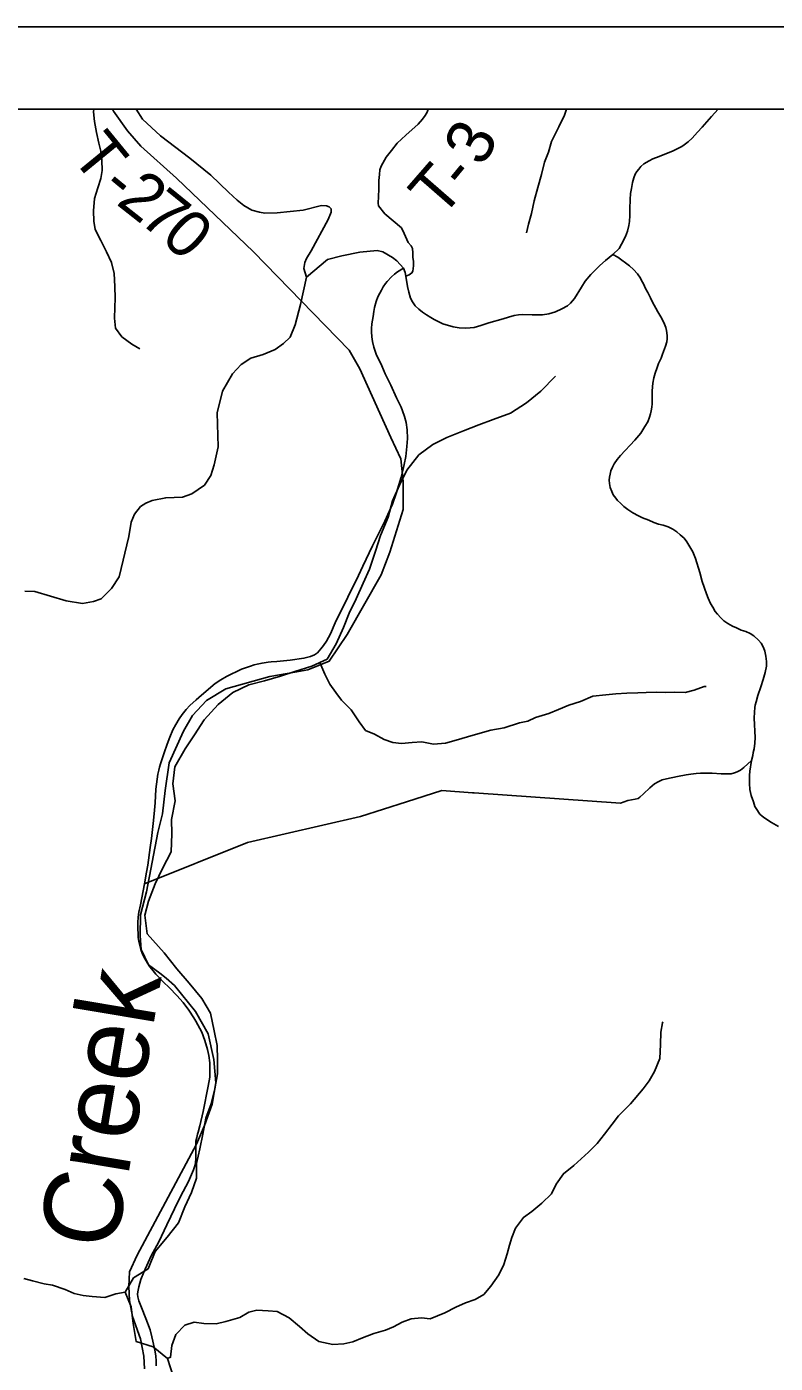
# Model space of a CAD drawing. Extents: x 0 to 34, y 0 to 22.
# Drawn here: x 2.84 to 3.746, y 19.381 to 21 of the extents above; entities that cross this region are included whole.
import ezdxf

# ---------------------------------------------------------------- set-up
doc = ezdxf.new("R2010")
doc.units = 0
for name, color, linetype in [('GM_X_County_Road', 7, 'Continuous'), ('GM_X_Minor_River', 7, 'Continuous'), ('GM_X_Minor_River_Text', 7, 'Continuous'), ('GM_X_Rail_Line', 7, 'Continuous'), ('GM_X_Township_Road', 7, 'Continuous'), ('GM_X_Township_Road_Text', 7, 'Continuous'), ('SH_Data', 7, 'Continuous')]:
    doc.layers.add(name, color=color, linetype=linetype)

msp = doc.modelspace()

# ---------------------------------------------------------------- linework, layer by layer
at = {"layer": 'GM_X_County_Road'}
msp.add_lwpolyline([(3.7501, 20.0312), (3.7416, 20.0362), (3.7334, 20.0413), (3.7303, 20.0439), (3.7276, 20.0464), (3.7258, 20.0486), (3.7245, 20.0509), (3.7216, 20.0556), (3.7197, 20.0611), (3.7172, 20.0689), (3.7156, 20.0762), (3.7149, 20.0833), (3.7151, 20.0889), (3.7151, 20.0931), (3.7155, 20.0985), (3.7174, 20.1112), (3.7189, 20.1175), (3.7196, 20.121), (3.7205, 20.1253), (3.7213, 20.1325), (3.7217, 20.1391), (3.7214, 20.1468), (3.7211, 20.155), (3.7208, 20.1624), (3.7211, 20.1698), (3.7216, 20.1757), (3.722, 20.1783), (3.7229, 20.1824), (3.7252, 20.1901), (3.7287, 20.2006), (3.7317, 20.2094), (3.7339, 20.2177), (3.7355, 20.2257), (3.7354, 20.2312), (3.7348, 20.2375), (3.7336, 20.2438), (3.7319, 20.2483), (3.729, 20.2536), (3.7261, 20.2572), (3.7201, 20.2624), (3.7158, 20.265), (3.7107, 20.2674), (3.7051, 20.2693), (3.6992, 20.272), (3.6943, 20.2742), (3.6887, 20.2772), (3.6841, 20.2804), (3.6803, 20.2839), (3.6763, 20.2884), (3.6735, 20.2919), (3.6705, 20.2969), (3.6677, 20.3016), (3.665, 20.3078), (3.6629, 20.3132), (3.6578, 20.3283), (3.6547, 20.339), (3.6495, 20.3559), (3.6462, 20.364), (3.6429, 20.3701), (3.6393, 20.376), (3.6358, 20.3804), (3.6312, 20.3848), (3.6271, 20.3882), (3.6223, 20.3914), (3.6167, 20.3942), (3.6106, 20.3963), (3.6049, 20.3977), (3.5993, 20.3995), (3.5931, 20.4022), (3.5855, 20.4052), (3.5807, 20.4075), (3.5736, 20.4112), (3.5675, 20.4153), (3.5627, 20.419), (3.5586, 20.4228), (3.5551, 20.4262), (3.5531, 20.429), (3.5501, 20.4331), (3.5482, 20.437), (3.5463, 20.4421), (3.5455, 20.4467), (3.5451, 20.4509), (3.5455, 20.4543), (3.5462, 20.458), (3.5472, 20.462), (3.5489, 20.4666), (3.5513, 20.4707), (3.5547, 20.4759), (3.5589, 20.4808), (3.5761, 20.4991), (3.5833, 20.5078), (3.5883, 20.5158), (3.5918, 20.5216), (3.594, 20.5273), (3.5953, 20.5313), (3.5961, 20.5348), (3.5966, 20.5391), (3.597, 20.5434), (3.5971, 20.5512), (3.597, 20.5554), (3.5972, 20.5588), (3.5975, 20.5638), (3.5979, 20.5685), (3.5993, 20.5746), (3.6006, 20.5804), (3.603, 20.5871), (3.605, 20.5922), (3.6079, 20.5987), (3.6098, 20.6034), (3.6122, 20.6097), (3.6133, 20.613), (3.6148, 20.6182), (3.6151, 20.6219), (3.6152, 20.6258), (3.615, 20.6291), (3.6145, 20.6321), (3.6137, 20.6357), (3.6119, 20.6398), (3.6088, 20.6466), (3.6041, 20.6547), (3.5973, 20.6674), (3.5951, 20.6715), (3.5918, 20.6783), (3.5891, 20.683), (3.5865, 20.6885), (3.5844, 20.6925), (3.5829, 20.6953), (3.5792, 20.7007), (3.5745, 20.7061), (3.5696, 20.7103), (3.5554, 20.721), (3.5493, 20.724)], dxfattribs=at)
at = {"layer": 'GM_X_Minor_River'}
for points in [[(2.9209, 20.9), (2.9206, 20.8969), (2.9217, 20.8852), (2.9244, 20.8719), (2.927, 20.859), (2.9293, 20.8492), (2.9308, 20.8382), (2.9312, 20.826), (2.9293, 20.8162), (2.9259, 20.8048), (2.9217, 20.7919), (2.9206, 20.7771), (2.9209, 20.7646), (2.9228, 20.7543), (2.9293, 20.7411), (2.9364, 20.7274), (2.9425, 20.7145), (2.9455, 20.7013), (2.9466, 20.6853), (2.947, 20.6713), (2.9466, 20.6599), (2.9462, 20.647), (2.9474, 20.6349), (2.9549, 20.6243), (2.967, 20.6156), (2.9768, 20.6099)], [(3.4935, 20.9), (3.491, 20.8927), (3.4842, 20.8787), (3.4751, 20.8612), (3.4717, 20.848), (3.4668, 20.8358), (3.463, 20.821), (3.4585, 20.8051), (3.4543, 20.7892), (3.4509, 20.7736), (3.4475, 20.7607), (3.4449, 20.7505)], [(3.4802, 20.5768), (3.4623, 20.5586), (3.4449, 20.5445), (3.4256, 20.532), (3.4047, 20.5244), (3.3873, 20.5179), (3.3687, 20.5107), (3.3486, 20.5024), (3.3316, 20.494), (3.3145, 20.4815), (3.3001, 20.4629), (3.291, 20.4446), (3.2826, 20.426), (3.2776, 20.4059), (3.2681, 20.3838), (3.262, 20.3648), (3.2548, 20.3431), (3.2472, 20.326), (3.2388, 20.307), (3.23, 20.2899), (3.2232, 20.2724), (3.2144, 20.2527), (3.2034, 20.234), (3.1848, 20.2257), (3.1644, 20.2192), (3.147, 20.2136), (3.1276, 20.2079), (3.1087, 20.2029), (3.0894, 20.1935), (3.0715, 20.179), (3.0545, 20.1604), (3.0427, 20.1425), (3.0317, 20.1254), (3.0191, 20.1038), (3.0168, 20.0832), (3.0194, 20.0623), (3.0152, 20.0399), (3.0155, 20.0224), (3.0147, 20.0007), (3.0041, 19.9806), (2.9953, 19.9619), (2.987, 19.941), (2.9828, 19.9239), (2.9857, 19.9015), (3.0061, 19.8783), (3.0216, 19.8588), (3.0363, 19.8417), (3.0518, 19.8231), (3.0624, 19.8052), (3.0668, 19.7839), (3.0702, 19.766), (3.0709, 19.7489), (3.0709, 19.7318), (3.0674, 19.7135), (3.0632, 19.6953), (3.0568, 19.6782), (3.0529, 19.6588), (3.0495, 19.6409), (3.0453, 19.6234), (3.0452, 19.6055), (3.0391, 19.588), (3.0311, 19.5709), (3.0235, 19.5512), (3.0099, 19.5341), (2.9954, 19.5166), (2.9867, 19.4957), (2.9692, 19.4847), (2.959, 19.4675), (2.9661, 19.4497), (2.9687, 19.4295), (2.9721, 19.4078), (2.9929, 19.4013), (3.0103, 19.3869), (3.0174, 19.3644)], [(3.1945, 20.23), (3.2007, 20.2159), (3.2067, 20.2037), (3.2142, 20.1938), (3.221, 20.1843), (3.2327, 20.1725), (3.2422, 20.1581), (3.2501, 20.1478), (3.261, 20.1432), (3.2724, 20.1368), (3.283, 20.1333), (3.2936, 20.1321), (3.3064, 20.1332), (3.3182, 20.1339), (3.3322, 20.1312), (3.3469, 20.1323), (3.3628, 20.1368), (3.3776, 20.1413), (3.4018, 20.1481), (3.4178, 20.1507), (3.4363, 20.157), (3.4465, 20.1589), (3.456, 20.1634), (3.4719, 20.1683), (3.4837, 20.1732), (3.4962, 20.1784), (3.5102, 20.1826), (3.5253, 20.1893), (3.5409, 20.1908), (3.5533, 20.1919), (3.5666, 20.193), (3.5798, 20.1933), (3.5897, 20.1937), (3.6018, 20.194), (3.6128, 20.1936), (3.6245, 20.1939), (3.637, 20.1935), (3.648, 20.1965), (3.6601, 20.201), (3.6627, 20.201)], [(3.0103, 19.3869), (3.014, 19.3886), (3.0155, 19.4026), (3.0201, 19.4163), (3.031, 19.4276), (3.0424, 19.4311), (3.0541, 19.4296), (3.0692, 19.4292), (3.0809, 19.4319), (3.0976, 19.4368), (3.1085, 19.4433), (3.1183, 19.4455), (3.132, 19.4448), (3.1429, 19.444), (3.1577, 19.4365), (3.1701, 19.4258), (3.18, 19.4171), (3.1936, 19.4077), (3.2106, 19.4042), (3.2238, 19.405), (3.2348, 19.4073), (3.2465, 19.4119), (3.2601, 19.4172), (3.2741, 19.4214), (3.2839, 19.4255), (3.2945, 19.4309), (3.3051, 19.435), (3.3176, 19.4362), (3.3281, 19.4351), (3.3459, 19.4423), (3.3595, 19.4491), (3.3712, 19.4544), (3.3826, 19.4586), (3.3932, 19.4647), (3.4019, 19.4746), (3.4113, 19.4882), (3.4177, 19.5011), (3.4215, 19.514), (3.4245, 19.5243), (3.4272, 19.5337), (3.4317, 19.5451), (3.4412, 19.558), (3.4514, 19.5652), (3.4635, 19.5751), (3.4752, 19.5865), (3.4809, 19.5983), (3.4896, 19.6108), (3.5024, 19.621), (3.5202, 19.637), (3.5304, 19.6476), (3.5395, 19.6586), (3.5486, 19.6708), (3.5565, 19.681), (3.5709, 19.6954), (3.5864, 19.7136), (3.5936, 19.7235), (3.6, 19.7345), (3.6064, 19.7504), (3.6072, 19.7675), (3.6076, 19.7823), (3.6098, 19.7937), (3.61, 19.7949)], [(2.959, 19.4675), (2.9475, 19.4655), (2.9343, 19.461), (2.9191, 19.4621), (2.9082, 19.4632), (2.8972, 19.4659), (2.8863, 19.4708), (2.8711, 19.4757), (2.8609, 19.4776), (2.8469, 19.481), (2.8364, 19.484)]]:
    msp.add_lwpolyline(points, dxfattribs=at)
at = {"layer": 'GM_X_Rail_Line'}
msp.add_lwpolyline([(2.9825, 19.3745), (2.9817, 19.3898), (2.9777, 19.4108), (2.968, 19.4381), (2.964, 19.4574), (2.9632, 19.4743), (2.964, 19.492), (2.9736, 19.5122), (3.0452, 19.6466), (3.0549, 19.6691), (3.0641, 19.6951), (3.0686, 19.7209), (3.0662, 19.7492), (3.0595, 19.7804), (3.0442, 19.8074), (3.0185, 19.8389), (3.0085, 19.8476), (3.0009, 19.8537), (2.9873, 19.8639), (2.9785, 19.8824), (2.9769, 19.8989), (2.9777, 19.9242), (2.9849, 19.9524), (2.9986, 20.024), (3.0042, 20.0469), (3.0073, 20.0748), (3.0122, 20.1085), (3.0294, 20.1467), (3.0404, 20.1657), (3.0576, 20.1839), (3.0808, 20.1981), (3.134, 20.2132), (3.1644, 20.2183), (3.1801, 20.2212), (3.2061, 20.2317), (3.2278, 20.2639), (3.2688, 20.3363), (3.2793, 20.3637), (3.2956, 20.4152), (3.2956, 20.4492), (3.2926, 20.4765), (3.2806, 20.5024), (3.2672, 20.5318), (3.2431, 20.5858), (3.2302, 20.6083), (3.1144, 20.7274), (3.0211, 20.8167), (2.978, 20.8554), (2.9619, 20.8739), (2.945, 20.8977), (2.9437, 20.9)], dxfattribs=at)
at = {"layer": 'GM_X_Township_Road'}
for points in [[(2.8374, 20.3162), (2.8496, 20.316), (2.8873, 20.3045), (2.9074, 20.3016), (2.9207, 20.3037), (2.9297, 20.307), (2.9424, 20.3195), (2.9517, 20.3336), (2.9632, 20.3825), (2.9661, 20.4001), (2.9703, 20.4095), (2.9776, 20.4189), (2.9841, 20.4231), (2.9916, 20.4264), (3.0081, 20.4295), (3.0282, 20.4304), (3.0397, 20.4344), (3.055, 20.4448), (3.0627, 20.4563), (3.0667, 20.4693), (3.0715, 20.4913), (3.0702, 20.5323), (3.0769, 20.5587), (3.0891, 20.5796), (3.0995, 20.5909), (3.1112, 20.5984), (3.126, 20.603), (3.1405, 20.609), (3.1507, 20.6162), (3.1589, 20.6239), (3.1649, 20.6388), (3.1712, 20.6635), (3.1784, 20.6968), (3.2038, 20.718), (3.2212, 20.7224), (3.2431, 20.7268), (3.264, 20.7291), (3.2711, 20.7274), (3.2828, 20.7205), (3.288, 20.7164), (3.2958, 20.7076), (3.2981, 20.7025), (3.2989, 20.6978), (3.301, 20.6855), (3.3026, 20.6784), (3.3045, 20.6714), (3.3069, 20.6668), (3.3102, 20.662), (3.3145, 20.6578), (3.3189, 20.6543), (3.3238, 20.651), (3.3291, 20.6478), (3.3332, 20.6456), (3.3395, 20.6422), (3.3436, 20.64), (3.3561, 20.6367), (3.3635, 20.6355), (3.3713, 20.635), (3.3767, 20.6353), (3.3814, 20.6359), (3.3897, 20.6383), (3.3993, 20.6413), (3.4168, 20.6463), (3.4231, 20.6482), (3.4301, 20.6501), (3.4351, 20.6509), (3.4398, 20.6513), (3.452, 20.6511), (3.4642, 20.6511), (3.472, 20.6523), (3.4801, 20.6549), (3.4879, 20.6584), (3.4945, 20.6619), (3.4982, 20.6653), (3.5031, 20.671), (3.5117, 20.6847), (3.5161, 20.6919), (3.523, 20.6998), (3.5272, 20.7045), (3.5339, 20.7109), (3.5405, 20.7169), (3.5493, 20.724), (3.5571, 20.7315), (3.5601, 20.7366), (3.5649, 20.7458), (3.5671, 20.7524), (3.5687, 20.7592), (3.5695, 20.7643), (3.57, 20.7713), (3.5701, 20.7795), (3.5703, 20.7906), (3.571, 20.7981), (3.5721, 20.804), (3.5734, 20.8115), (3.575, 20.817), (3.5767, 20.8215), (3.5787, 20.8245), (3.5808, 20.8275), (3.5833, 20.8308), (3.5872, 20.8339), (3.5933, 20.8377), (3.5978, 20.84), (3.6056, 20.843), (3.6225, 20.8495), (3.6289, 20.8529), (3.6331, 20.8551), (3.6357, 20.8568), (3.6406, 20.8607), (3.6455, 20.8651), (3.6522, 20.8725), (3.6575, 20.8784), (3.6688, 20.8912), (3.6769, 20.9)], [(3.1784, 20.6968), (3.1755, 20.7072), (3.1764, 20.7145), (3.1785, 20.7191), (3.1842, 20.7287), (3.2046, 20.7667), (3.2083, 20.7755), (3.2082, 20.7793), (3.2058, 20.7819), (3.2028, 20.7831), (3.1966, 20.7833), (3.1746, 20.7779), (3.143, 20.7747), (3.1281, 20.7744), (3.1215, 20.7756), (3.1123, 20.778), (3.1027, 20.7835), (3.0947, 20.7898), (3.0842, 20.7998), (3.0627, 20.8202), (3.0373, 20.8407), (3.0017, 20.868), (2.98, 20.8882), (2.9723, 20.9)], [(3.2989, 20.6978), (3.3029, 20.6994), (3.3061, 20.7018), (3.3072, 20.7039), (3.3081, 20.7104), (3.3081, 20.7155), (3.3072, 20.7208), (3.3075, 20.7262), (3.3068, 20.7313), (3.3052, 20.7346), (3.3016, 20.7388), (3.297, 20.7497), (3.2937, 20.7564), (3.2732, 20.7735), (3.2657, 20.7832), (3.2653, 20.7863), (3.2658, 20.7942), (3.2661, 20.8033), (3.2662, 20.8137), (3.2669, 20.8211), (3.2674, 20.8265), (3.269, 20.8311), (3.2752, 20.8419), (3.2814, 20.8501), (3.2885, 20.8589), (3.299, 20.8688), (3.3137, 20.882), (3.3189, 20.8879), (3.3221, 20.8924), (3.3245, 20.8966), (3.3259, 20.9)], [(3.0095, 19.5488), (3.0234, 19.5783), (3.0293, 19.5894), (3.0355, 19.6014), (3.0417, 19.6156), (3.0432, 19.6206), (3.044, 19.6242), (3.0444, 19.6295), (3.0445, 19.6382), (3.0445, 19.6461), (3.0447, 19.6504), (3.0457, 19.6548), (3.0464, 19.6589), (3.0474, 19.6613), (3.0492, 19.6687), (3.0535, 19.6863), (3.0594, 19.7168), (3.0614, 19.7279), (3.0616, 19.7364), (3.0615, 19.7452), (3.0604, 19.7539), (3.0586, 19.7614), (3.0554, 19.772), (3.0516, 19.7822), (3.0447, 19.7956), (3.0422, 19.7998), (3.036, 19.8089), (3.0291, 19.8183), (3.0214, 19.8266), (3.0126, 19.836), (3.005, 19.8431), (3.0004, 19.8482), (2.9961, 19.8526), (2.9928, 19.8565), (2.989, 19.8613), (2.986, 19.8658), (2.9831, 19.8707), (2.98, 19.8769), (2.9779, 19.8824), (2.9756, 19.8922), (2.9748, 19.8975), (2.9745, 19.9027), (2.9743, 19.9064), (2.9743, 19.9103), (2.9743, 19.915), (2.9747, 19.9217), (2.9756, 19.9276), (2.9774, 19.9366), (2.9823, 19.9621), (2.9848, 19.9762), (2.9862, 19.9845), (2.9893, 20.0059), (2.9908, 20.0167), (2.9929, 20.0351), (2.9942, 20.0469), (2.9951, 20.0602), (2.9962, 20.0764), (2.9977, 20.0886), (2.9986, 20.0948), (2.9998, 20.0997), (3.0007, 20.1034), (3.0017, 20.1071), (3.006, 20.1205), (3.0098, 20.1312), (3.0129, 20.1395), (3.0167, 20.1485), (3.0204, 20.155), (3.0242, 20.1616), (3.0279, 20.1669), (3.0329, 20.173), (3.0374, 20.178), (3.0449, 20.1849), (3.0481, 20.1875), (3.06, 20.1977), (3.0681, 20.2046), (3.0746, 20.2091), (3.0818, 20.2132), (3.0997, 20.2219), (3.1057, 20.2241), (3.1106, 20.2257), (3.115, 20.227), (3.1189, 20.2281), (3.1247, 20.2293), (3.132, 20.2303), (3.1357, 20.2307), (3.1428, 20.2313), (3.1586, 20.2328), (3.1754, 20.2351), (3.1834, 20.2372), (3.1881, 20.2394), (3.1919, 20.2418), (3.1958, 20.2465), (3.1992, 20.2504), (3.2026, 20.2559), (3.2074, 20.2649), (3.2134, 20.2779), (3.2286, 20.3091), (3.2414, 20.3353), (3.2469, 20.3468), (3.2586, 20.3711), (3.2659, 20.3859), (3.2734, 20.4012), (3.2827, 20.4219), (3.2877, 20.4357), (3.293, 20.4544), (3.2951, 20.4627), (3.2967, 20.47), (3.2989, 20.4793), (3.3001, 20.4917), (3.3009, 20.5011), (3.3003, 20.5116), (3.2992, 20.5208), (3.2972, 20.5281), (3.2948, 20.5347), (3.293, 20.5393), (3.2877, 20.5507), (3.2808, 20.566), (3.2738, 20.5798), (3.2696, 20.5892), (3.2629, 20.6036), (3.2601, 20.6119), (3.2585, 20.6187), (3.2578, 20.6246), (3.2574, 20.6304), (3.2573, 20.6344), (3.2578, 20.6403), (3.2593, 20.6492), (3.2601, 20.6553), (3.261, 20.6598), (3.2628, 20.6671), (3.265, 20.6729), (3.2674, 20.6775), (3.2693, 20.6808), (3.2715, 20.6851), (3.2742, 20.6889), (3.2762, 20.6916), (3.2813, 20.6972), (3.2852, 20.7005), (3.2887, 20.703), (3.2958, 20.7076)], [(3.3816, 20.0722), (3.5586, 20.0597), (3.5676, 20.0627), (3.5766, 20.0646), (3.5801, 20.0653), (3.5823, 20.0671), (3.5867, 20.0711), (3.5944, 20.0781), (3.6001, 20.0831), (3.6042, 20.0856), (3.6092, 20.0877), (3.6145, 20.0891), (3.6278, 20.0918), (3.6383, 20.0939), (3.6441, 20.0947), (3.6504, 20.0954), (3.6555, 20.0958), (3.6598, 20.0961), (3.6697, 20.0959), (3.6805, 20.0952), (3.6855, 20.095), (3.693, 20.0953), (3.6969, 20.0964), (3.7, 20.0974), (3.7042, 20.0998), (3.7081, 20.1027), (3.7174, 20.1112)], [(2.9823, 19.9621), (3.107, 20.0118), (3.2438, 20.0434), (3.2996, 20.0612), (3.3426, 20.0749), (3.3797, 20.0723), (3.3816, 20.0722)], [(2.9965, 19.378), (2.9964, 19.3843), (2.9961, 19.39), (2.9952, 19.3952), (2.9941, 19.4008), (2.9926, 19.4079), (2.9914, 19.4134), (2.9892, 19.4216), (2.9841, 19.4354), (2.9786, 19.449), (2.9753, 19.4569), (2.9743, 19.4619), (2.9739, 19.4648), (2.9744, 19.4679), (2.9755, 19.4738), (2.9781, 19.4827), (2.9814, 19.4917), (2.9906, 19.5114), (2.9998, 19.5282), (3.0095, 19.5488)]]:
    msp.add_lwpolyline(points, dxfattribs=at)
at = {"layer": 'SH_Data'}
for p, q in [((2, 21), (9, 21)), ((2.1, 20.9), (8.9, 20.9))]:
    msp.add_line(p, q, dxfattribs=at)

# ---------------------------------------------------------------- texts
at = {"layer": 'GM_X_Minor_River_Text'}
msp.add_text('Creek', height=0.0947, rotation=80.4921, dxfattribs=at).set_placement((2.9472, 19.516))
at = {"layer": 'GM_X_Township_Road_Text'}
for s, rotation, p in [('3', 62.8739, (3.3926, 20.829)), ('T', 309.2829, (2.8921, 20.843)), ('T', 48.938, (3.3414, 20.7666)), ('-', 320.4799, (2.9276, 20.8015)), ('2', 321.8, (2.9467, 20.7858)), ('-', 50.337, (3.3703, 20.7998)), ('7', 320.9607, (2.974, 20.7643)), ('0', 317.1494, (3.0004, 20.7429))]:
    msp.add_text(s, height=0.0568, rotation=rotation, dxfattribs=at).set_placement(p)

doc.saveas('drawing.dxf')
